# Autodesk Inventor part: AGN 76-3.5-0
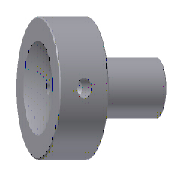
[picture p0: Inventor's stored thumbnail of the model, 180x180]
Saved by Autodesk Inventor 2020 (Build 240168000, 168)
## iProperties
IsCustomPart: 1
Created: 2019-01
Part Number: AGN 76-3.5-0
Material: DIN 1.2312
Description: Sprue Bushing
Document SubType Name: Modeling
Designer: LENOVO-CADCIM
Standard Revision: 1
Manufacturer: DME
Language: en-US
Size Designation: 76-3.5-0
Categories: <MemberInstance><Categories><Category DisplayName="Mold" InternalName="349578f2-f4d4-4954-8c09-8e99297a61c0" Mnemonic="MOLD"><Category DisplayName="Runners" Int
Density: 7.85 g/cm^3
Appearance: Default
Mass: 529.137 g
Surface Area: 115.001 cm^2
Volume: 67.406 cm^3
Author: LENOVO-CADCIM
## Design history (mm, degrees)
sketch "Sketch1"
  geometry: L1 (0, -27.2)-(0, 23.2) reference; L2 (1.75, 20)-(19, 20); L3 (19, 20)-(19, 0); L4 (19, 0)-(12, 0); L5 (9, -3)-(9, -76); L6 (9, -76)-(4.264, -76); L7 (4.264, -76)-(1.75, 20); A1 r 3 centre (12, -3) between (12, 0) and (9, -3); 2 further points
  constraints: 12 end point, 3 parallel, 2 perpendicular, 2 point on circle, 2 point on line, 2 tangent, 1 centre point
  dimensions: "d0" = 18 diameter of L5 L1 (= D); "d3" = 38 diameter of L3 L1 (= d1); "d6" = 1.5 deg angle of L7 L1 (= 0.5 x Taper); "d7" = 20 distance between parallel lines of L4 L2 (= K_); "d8" = 76 distance between parallel lines of L4 L6 (= L); "d9" = 3 radius of A1 (= R3); "d62" = 3.5 diameter of point (1.75, 20) L1 (= d_); "d63" = 0 distance from line of point (1.75, 20) L2 (computed from Rd)
revolve "Revolution1" sketch "Sketch1" stored, may be unused: angle "d10" = 90 deg
sketch "Sketch2"
  geometry: L1 (0, -32.79)-(0, 56.739) reference; L2 (4.264, -76)-(1.75, 20) reference; L3 (-19, 20)-(19, 20) reference; L4 (0, 50.901)-(0, 19.901); A1 r 15.5 centre (0, 35.401) between (0, 19.901) and (0, 50.901); 2 further points
  constraints: 3 point on circle, 3 point on line, 2 end point, 1 centre point, 1 midpoint
  dimensions: "d64" = 0 distance from line of point (1.75, 20) L3 (computed from Rd); "d67" = 15.5 radius of A1 (= Rk)
revolve "Revolution2" sketch "Sketch2" stored, may be unused: angle "d13" = 90 deg
workplane "Work Plane1"
sketch "Sketch3"
  geometry: 2 further points
  constraints: 1 vertical alignment
  dimensions: "d43" = 10 distance of point (0, -10) point (0, 0) (= 0.5 x K_)
hole "Hole1" sketch "Sketch3" at (0, 0) diameter "d15" = 4 (= pd1); stored, may be unused: countersink angle "d19" = 90 deg, drill point angle "d21" = 118 deg; dims "d16" = 6, "d17" = 4, "d18" = 2, "d20" = 6 (= pl1)
chamfer "Chamfer1" distance "d22" = 0.3; stored, may be unused: second distance "d23" = 2, angle "d24" = 45 deg
sketch "Sketch4"
  geometry: L1 (0, -30.4)-(0, 42.4) reference; L2 (0, 40)-(19.5, 40); L3 (19.5, 40)-(19.5, 0); L4 (9, -76)-(0, -76); L5 (0, -76)-(0, 40); L6 (9, -3)-(9, -76); L7 (12, 0)-(19.5, 0); L8 (12, 0)-(9, -3); 2 further points
  constraints: 14 end point, 4 point on line, 2 horizontal, 2 parallel, 1 perpendicular, 1 vertical
  dimensions: "d56" = 3 distance of L7.start point (9, 0) (= R3_CS); "d57" = 3 distance of L6.start point (9, 0) (= d56); "d58" = 39 diameter of L3 L1 (= d1_CS); "d59" = 40 distance between parallel lines of L7 L2 (= K_CS); "d60" = 18 diameter of L6 L1 (= D_CS); "d61" = 76 distance between parallel lines of L7 L4 (= L_CS)
feature "RevolutionSrf1" sketch "Sketch4" dims angle "d33" = 90 deg
body "Solid1"
body "Srf1"
other parameters: "L" = 76 [user parameter; used in 1 equation term], "d1" = 38 [user parameter; used in 1 equation term], "d_" = 3.5 [user parameter; used in 1 equation term], "D" = 18 [user parameter; used in 1 equation term], "K_" = 20 [user parameter; used in 2 equation terms], "R" = 0 [user parameter], "Taper" = 3 deg [user parameter; used in 1 equation term], "Rd" = 0 [user parameter; used in 2 equation terms], "R3" = 3 [user parameter; used in 1 equation term], "pd1" = 4 [user parameter; used in 1 equation term], "d1_CS" = 39 [user parameter; used in 1 equation term], "K_CS" = 40 [user parameter; used in 1 equation term], "d44" = 0, "d45" = 0, "d46" = 0, "L_CS" = 76 [user parameter; used in 1 equation term], "D_CS" = 18 [user parameter; used in 1 equation term], "pl1" = 6 [user parameter; used in 1 equation term], "R3_CS" = 3 [user parameter; used in 1 equation term], "Rk" = 15.5 [user parameter; used in 1 equation term]
